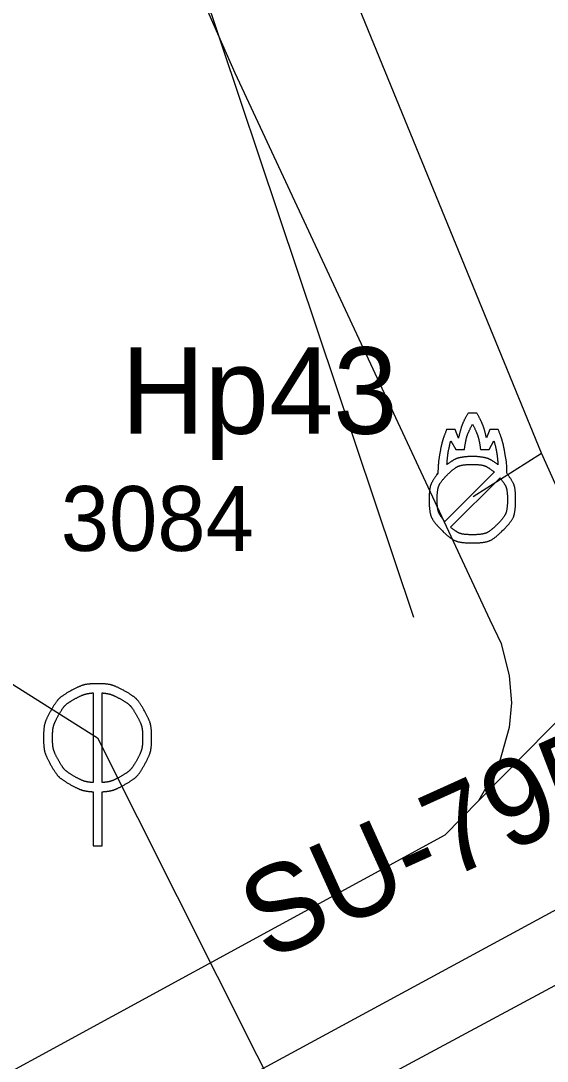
# Model space of a CAD drawing. Extents: x -562248 to -562040, y -1079385 to -1079027.
# Drawn here: x -562092.87 to -562080.7, y -1079266.81 to -1079242.75 of the extents above; entities that cross this region are included whole.
import ezdxf

# ---------------------------------------------------------------- set-up
doc = ezdxf.new("R2010")
doc.units = 0
for name, color, linetype in [('Armatura - popis', 7, 'Continuous'), ('Default', 7, 'Continuous'), ('Hydrant', 7, 'Continuous'), ('Kanalizační stoka', 7, 'Continuous'), ('Kanalizační šachta', 7, 'Continuous'), ('Označení hydrantu', 7, 'Continuous'), ('Parcela-polygon', 7, 'Continuous'), ('Parcela-text', 7, 'Continuous'), ('Vodovodní řad', 7, 'Continuous')]:
    doc.layers.add(name, color=color, linetype=linetype)

msp = doc.modelspace()

# ---------------------------------------------------------------- linework, layer by layer
at = {"layer": 'Default'}
for points in [[(-562082.535, -1079251.825), (-562082.633, -1079251.997), (-562082.706, -1079252.189), (-562082.756, -1079252.4)], [(-562082.107, -1079252.398), (-562082.158, -1079252.187), (-562082.232, -1079251.996), (-562082.33, -1079251.825)], [(-562082.617, -1079252.667), (-562082.59, -1079252.459), (-562082.528, -1079252.263), (-562082.432, -1079252.079)], [(-562082.432, -1079252.079), (-562082.335, -1079252.264), (-562082.273, -1079252.46), (-562082.246, -1079252.667)], [(-562083.031, -1079252.206), (-562083.101, -1079252.385), (-562083.153, -1079252.564), (-562083.185, -1079252.743)], [(-562081.68, -1079252.745), (-562081.713, -1079252.564), (-562081.765, -1079252.385), (-562081.834, -1079252.206)], [(-562083.023, -1079253.015), (-562083.009, -1079252.83), (-562082.979, -1079252.646), (-562082.934, -1079252.462)], [(-562081.934, -1079252.462), (-562081.887, -1079252.646), (-562081.856, -1079252.831), (-562081.842, -1079253.017)], [(-562082.525, -1079252.829), (-562082.713, -1079252.844), (-562082.879, -1079252.905), (-562083.023, -1079253.015)], [(-562081.842, -1079253.017), (-562081.988, -1079252.907), (-562082.154, -1079252.845), (-562082.342, -1079252.829)], [(-562083.217, -1079252.945), (-562083.222, -1079253.017), (-562083.227, -1079253.107), (-562083.232, -1079253.214)], [(-562083.011, -1079253.248), (-562082.852, -1079253.09), (-562082.661, -1079253.011), (-562082.435, -1079253.011)], [(-562082.435, -1079253.011), (-562082.241, -1079253.011), (-562082.072, -1079253.07), (-562081.928, -1079253.187)], [(-562081.633, -1079253.224), (-562081.637, -1079253.138), (-562081.639, -1079253.087), (-562081.641, -1079253.072)], [(-562083.232, -1079253.22), (-562083.366, -1079253.393), (-562083.434, -1079253.596), (-562083.434, -1079253.827)], [(-562083.232, -1079253.214), (-562083.243, -1079253.226), (-562083.253, -1079253.238), (-562083.264, -1079253.249)], [(-562083.248, -1079253.823), (-562083.248, -1079253.598), (-562083.169, -1079253.406), (-562083.011, -1079253.248)], [(-562081.795, -1079253.32), (-562081.68, -1079253.463), (-562081.623, -1079253.631), (-562081.623, -1079253.823)], [(-562081.434, -1079253.827), (-562081.434, -1079253.598), (-562081.5, -1079253.397), (-562081.633, -1079253.224)], [(-562083.434, -1079253.827), (-562083.434, -1079254.103), (-562083.336, -1079254.339), (-562083.141, -1079254.533)], [(-562083.072, -1079254.331), (-562083.189, -1079254.187), (-562083.248, -1079254.017), (-562083.248, -1079253.823)], [(-562081.623, -1079253.823), (-562081.623, -1079254.049), (-562081.702, -1079254.24), (-562081.861, -1079254.399)], [(-562081.726, -1079254.533), (-562081.531, -1079254.339), (-562081.434, -1079254.103), (-562081.434, -1079253.827)], [(-562083.141, -1079254.533), (-562082.945, -1079254.728), (-562082.71, -1079254.825), (-562082.435, -1079254.825)], [(-562082.435, -1079254.636), (-562082.628, -1079254.636), (-562082.796, -1079254.579), (-562082.939, -1079254.464)], [(-562081.861, -1079254.399), (-562082.02, -1079254.557), (-562082.212, -1079254.636), (-562082.435, -1079254.636)], [(-562082.435, -1079254.825), (-562082.158, -1079254.825), (-562081.922, -1079254.728), (-562081.726, -1079254.533)], [(-562091.1, -1079258.08), (-562091.312, -1079258.08), (-562091.517, -1079258.134), (-562091.715, -1079258.241)], [(-562090.486, -1079258.241), (-562090.685, -1079258.134), (-562090.89, -1079258.08), (-562091.1, -1079258.08)], [(-562091.715, -1079258.241), (-562091.914, -1079258.349), (-562092.069, -1079258.502), (-562092.182, -1079258.703)], [(-562091.615, -1079258.424), (-562091.472, -1079258.348), (-562091.334, -1079258.304), (-562091.203, -1079258.292)], [(-562090.997, -1079258.292), (-562090.866, -1079258.304), (-562090.729, -1079258.348), (-562090.587, -1079258.424)], [(-562090.018, -1079258.703), (-562090.131, -1079258.502), (-562090.287, -1079258.349), (-562090.486, -1079258.241)], [(-562092.003, -1079258.809), (-562091.911, -1079258.642), (-562091.781, -1079258.514), (-562091.615, -1079258.424)], [(-562090.587, -1079258.424), (-562090.421, -1079258.514), (-562090.291, -1079258.642), (-562090.198, -1079258.809)], [(-562092.182, -1079258.703), (-562092.294, -1079258.903), (-562092.35, -1079259.112), (-562092.35, -1079259.33)], [(-562092.142, -1079259.33), (-562092.142, -1079259.149), (-562092.096, -1079258.976), (-562092.003, -1079258.809)], [(-562090.198, -1079258.809), (-562090.104, -1079258.976), (-562090.058, -1079259.149), (-562090.058, -1079259.33)], [(-562089.85, -1079259.33), (-562089.85, -1079259.112), (-562089.906, -1079258.903), (-562090.018, -1079258.703)], [(-562092.35, -1079259.33), (-562092.35, -1079259.546), (-562092.295, -1079259.754), (-562092.185, -1079259.953)], [(-562092.006, -1079259.848), (-562092.097, -1079259.683), (-562092.142, -1079259.511), (-562092.142, -1079259.33)], [(-562090.058, -1079259.33), (-562090.058, -1079259.511), (-562090.103, -1079259.683), (-562090.194, -1079259.848)], [(-562090.015, -1079259.953), (-562089.905, -1079259.754), (-562089.85, -1079259.546), (-562089.85, -1079259.33)], [(-562091.62, -1079260.231), (-562091.786, -1079260.14), (-562091.915, -1079260.012), (-562092.006, -1079259.848)], [(-562090.194, -1079259.848), (-562090.285, -1079260.012), (-562090.413, -1079260.14), (-562090.578, -1079260.231)], [(-562092.185, -1079259.953), (-562092.075, -1079260.151), (-562091.921, -1079260.305), (-562091.723, -1079260.414)], [(-562090.477, -1079260.414), (-562090.279, -1079260.305), (-562090.125, -1079260.151), (-562090.015, -1079259.953)], [(-562091.203, -1079260.365), (-562091.339, -1079260.355), (-562091.478, -1079260.311), (-562091.62, -1079260.231)], [(-562090.578, -1079260.231), (-562090.721, -1079260.311), (-562090.861, -1079260.355), (-562090.997, -1079260.365)], [(-562091.723, -1079260.414), (-562091.548, -1079260.512), (-562091.375, -1079260.566), (-562091.203, -1079260.578)], [(-562090.997, -1079260.578), (-562090.825, -1079260.566), (-562090.652, -1079260.512), (-562090.477, -1079260.414)]]:
    msp.add_open_spline(points, degree=2, dxfattribs=at)
at = {"layer": 'Hydrant'}
for points in [[(-562082.33, -1079251.825), (-562082.535, -1079251.825)], [(-562082.756, -1079252.4), (-562082.834, -1079252.206), (-562083.031, -1079252.206)], [(-562081.834, -1079252.206), (-562082.033, -1079252.206), (-562082.107, -1079252.398)], [(-562082.934, -1079252.462), (-562082.816, -1079252.667), (-562082.617, -1079252.667)], [(-562082.246, -1079252.667), (-562082.047, -1079252.667), (-562081.934, -1079252.462)], [(-562083.185, -1079252.743), (-562083.217, -1079252.945)], [(-562082.342, -1079252.829), (-562082.525, -1079252.829)], [(-562081.641, -1079253.072), (-562081.648, -1079252.948), (-562081.68, -1079252.745)], [(-562083.264, -1079253.249), (-562083.232, -1079253.22)], [(-562081.928, -1079253.187), (-562083.072, -1079254.331)], [(-562082.939, -1079254.464), (-562081.795, -1079253.32)]]:
    msp.add_lwpolyline(points, dxfattribs=at)
at = {"layer": 'Kanalizační stoka'}
for points in [[(-562083.791, -1079256.552), (-562098.95, -1079211.35)], [(-562104.57, -1079250.84), (-562098.59, -1079254.61), (-562098.276, -1079254.807), (-562091.1, -1079259.33)], [(-562091.1, -1079259.33), (-562086.49, -1079268.51)], [(-562077.25, -1079263.3), (-562101.861, -1079276.526), (-562138.86, -1079296.41)]]:
    msp.add_lwpolyline(points, dxfattribs=at)
at = {"layer": 'Kanalizační šachta'}
for points in [[(-562091.203, -1079258.292), (-562091.203, -1079260.365)], [(-562090.997, -1079260.365), (-562090.997, -1079258.292)], [(-562091.203, -1079261.83), (-562090.997, -1079261.83), (-562090.997, -1079260.578)], [(-562091.203, -1079260.578), (-562091.203, -1079261.83)]]:
    msp.add_lwpolyline(points, dxfattribs=at)
at = {"layer": 'Parcela-polygon'}
for points in [[(-562092.25, -1079234.14), (-562087.93, -1079243.96), (-562082.03, -1079256.6), (-562081.77, -1079257.15), (-562081.58, -1079257.9), (-562081.53, -1079258.52), (-562081.58, -1079259.09), (-562081.83, -1079259.97), (-562082.29, -1079260.79), (-562083.07, -1079261.58), (-562094.62, -1079267.87), (-562113.94, -1079278.46), (-562115.46, -1079274.84), (-562111.34, -1079272.6), (-562096.55, -1079264.55), (-562101.14, -1079256.08), (-562102.73, -1079253.17), (-562100.18, -1079251.98), (-562102.28, -1079247.51), (-562093.4, -1079243.66), (-562099.13, -1079230.34)], [(-562092.25, -1079234.14), (-562087.93, -1079243.96), (-562082.03, -1079256.6), (-562081.77, -1079257.15), (-562081.58, -1079257.9), (-562081.53, -1079258.52), (-562081.58, -1079259.09), (-562081.83, -1079259.97), (-562082.29, -1079260.79), (-562074.7, -1079253.09), (-562081.96, -1079237.32)], [(-562050.734, -1079242.89), (-562074.7, -1079253.09), (-562082.29, -1079260.79), (-562083.07, -1079261.58), (-562094.62, -1079267.87), (-562113.94, -1079278.46), (-562131.57, -1079288.07), (-562135.96, -1079290.46), (-562143.99, -1079294.84), (-562166.66, -1079307.21), (-562184.27, -1079316.57), (-562201.76, -1079326), (-562209.06, -1079330.03), (-562233.192, -1079343.166)]]:
    msp.add_lwpolyline(points, dxfattribs=at)
at = {"layer": 'Vodovodní řad'}
for points in [[(-562076.873, -1079261.222), (-562077.411, -1079260.349), (-562080.838, -1079252.747), (-562088.062, -1079235.093), (-562089.377, -1079232.32), (-562093.695, -1079222.062)], [(-562082.418, -1079253.755), (-562080.838, -1079252.747)], [(-562205.614, -1079330.519), (-562174.097, -1079314.233), (-562147.992, -1079299.695), (-562146.568, -1079298.894), (-562118.26, -1079283.525), (-562104.098, -1079276.026), (-562101.887, -1079274.855), (-562091.855, -1079269.457), (-562077.721, -1079261.793), (-562076.873, -1079261.222)]]:
    msp.add_lwpolyline(points, dxfattribs=at)

# ---------------------------------------------------------------- texts
at = {"layer": 'Armatura - popis'}
msp.add_text('SU-795', height=2, rotation=24.3274, dxfattribs=at).set_placement((-562087.191, -1079264.509))
at = {"layer": 'Označení hydrantu'}
msp.add_text('Hp43', height=2, dxfattribs=at).set_placement((-562090.556, -1079252.302))
at = {"layer": 'Parcela-text'}
msp.add_text('3084', height=1.5, dxfattribs=at).set_placement((-562091.95, -1079255.01))

doc.saveas('drawing.dxf')
